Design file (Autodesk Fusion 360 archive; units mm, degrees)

design "VMS"
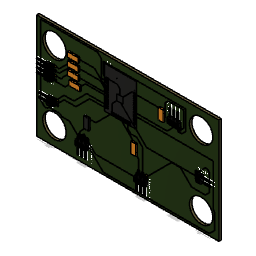
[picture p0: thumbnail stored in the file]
sketch "Outline" plane through (0, 0, 0) normal (0, 0, 1) x axis (1, 0, 0)
  line L1 (118, 0) -> (0, 0)
  line L2 (118, 68) -> (118, 0)
  line L3 (0, 68) -> (118, 68)
  line L4 (0, 0) -> (0, 68)
canvas "Canvas1" bodies "Board"
canvas "Canvas2" bodies "Board"
pcbhole "PCBHole1" HoleDepth 1.605 HoleDiameter 15.142 TipAngle 10313.2
pcbhole "PCBHole2" HoleDepth 1.605 HoleDiameter 15.142 TipAngle 10313.2
pcbhole "PCBHole3" HoleDepth 1.605 HoleDiameter 15.142 TipAngle 10313.2
pcbhole "PCBHole4" HoleDepth 1.605 HoleDiameter 15.142 TipAngle 10313.2
pcbhole "PCBHole5" HoleDepth 1.605 HoleDiameter 0.35 TipAngle 10313.2
pcbhole "PCBHole6" HoleDepth 1.605 HoleDiameter 0.35 TipAngle 10313.2
pcbhole "PCBHole7" HoleDepth 1.605 HoleDiameter 0.35 TipAngle 10313.2
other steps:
base_feature "Base Feature1"
base_feature "Base Feature1"
box_primitive "BoxPrimitive1" DistanceX 7.0612 DistanceY 3.2004 DistanceZ 1 OffsetDistanceX 0 OffsetDistanceY 0
pcbextrude "PCBExtrude1"
pcbextrude "PCBExtrude1"
base_feature "Base Feature1"
box_primitive "BoxPrimitive1" DistanceX 20.69 DistanceY 26.905 DistanceZ 0.1 OffsetDistanceX 0 OffsetDistanceY 0
extrude "Extrude1" sketch "Outline" blind 1.5 bodies "Board"
pcbextrude "PCBExtrude1"
pcbextrude "PCBExtrude1"
pcbhole "PCBHole1" HoleDepth 1.606 HoleDiameter 15.142 TipAngle 10313.2
pcbhole "PCBHole1" HoleDepth 1.606 HoleDiameter 15.142 TipAngle 10313.2
pcbhole "PCBHole2" HoleDepth 1.606 HoleDiameter 15.142 TipAngle 10313.2
pcbhole "PCBHole2" HoleDepth 1.606 HoleDiameter 15.142 TipAngle 10313.2
pcbhole "PCBHole3" HoleDepth 1.606 HoleDiameter 15.142 TipAngle 10313.2
pcbhole "PCBHole3" HoleDepth 1.606 HoleDiameter 15.142 TipAngle 10313.2
pcbhole "PCBHole4" HoleDepth 1.606 HoleDiameter 15.142 TipAngle 10313.2
pcbhole "PCBHole4" HoleDepth 1.606 HoleDiameter 15.142 TipAngle 10313.2
pcbhole "PCBHole5" HoleDepth 1.606 HoleDiameter 0.35 TipAngle 10313.2
pcbhole "PCBHole5" HoleDepth 1.606 HoleDiameter 0.35 TipAngle 10313.2
pcbhole "PCBHole6" HoleDepth 1.606 HoleDiameter 0.35 TipAngle 10313.2
pcbhole "PCBHole6" HoleDepth 1.606 HoleDiameter 0.35 TipAngle 10313.2
pcbhole "PCBHole7" HoleDepth 1.606 HoleDiameter 0.35 TipAngle 10313.2
pcbhole "PCBHole7" HoleDepth 1.606 HoleDiameter 0.35 TipAngle 10313.2
pcbextrude "PCBExtrude1"
pcbextrude "PCBExtrude2" bodies "CopperHoles"
create_component "CreateComponent1"
create_component "CreateComponent2"
create_component "CreateComponent3"
create_component "CreateComponent4"
create_component "CreateComponent5"
create_component "CreateComponent6"
as_built_joint "As-built1"
create_component "CreateComponent3"
create_component "CreateComponent4"
create_component "CreateComponent9"
create_component "CreateComponent10"
create_component "CreateComponent11"
named bodies: "Board", "CopperHoles"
